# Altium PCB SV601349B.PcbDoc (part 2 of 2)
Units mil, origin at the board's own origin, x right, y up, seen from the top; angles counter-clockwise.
Board outline 3013 x 3112 mil, 4 copper layers (TOP, GND, PWR, BOTTOM), stack 60.36 mil thick; 123 components, 67 nets, 345 pads, 132 vias.
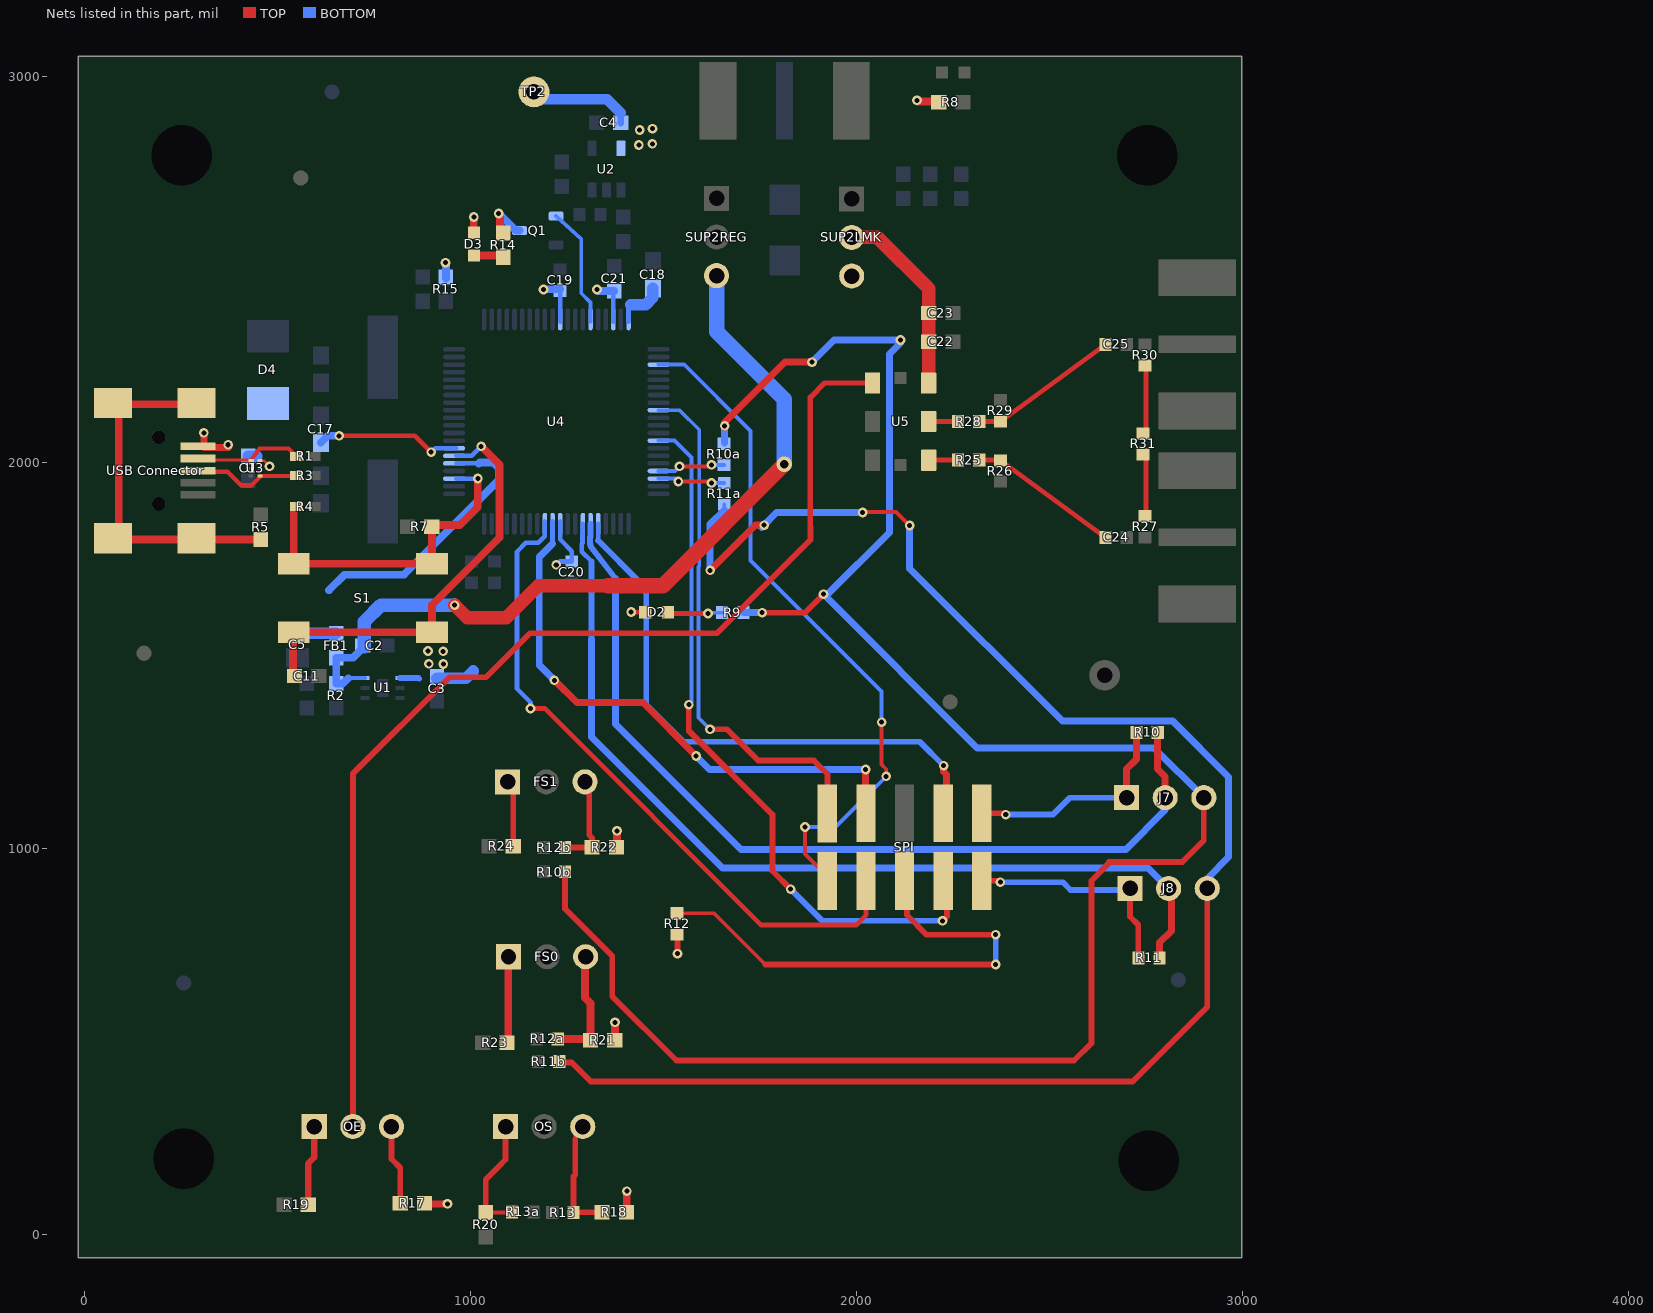
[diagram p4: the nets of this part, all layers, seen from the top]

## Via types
v1: diameter 25, hole 13, TOP to BOTTOM, 129 vias
v2: diameter 19.68, hole 7.87, TOP to BOTTOM, tented top, 1 vias
v3: diameter 40, hole 22, TOP to BOTTOM, 1 vias
v4: diameter 21, hole 9, TOP to BOTTOM, 1 vias

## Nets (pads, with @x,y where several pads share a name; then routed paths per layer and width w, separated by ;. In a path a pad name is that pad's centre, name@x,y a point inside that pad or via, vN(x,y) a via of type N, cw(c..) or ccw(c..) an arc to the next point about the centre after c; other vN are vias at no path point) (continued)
NetD2_2: D2.2 R9.2 | length 142
  TOP w10: D2.2@1511.53,1611 D2.2@1514.53,1608
  TOP w12: D2.2@1514.53,1608 v1(1615,1608)
  BOTTOM w10: v1(1615,1608) 1617,1610 R9.2@1651.44,1610
NetD3_2: D3.2 R14.2 | length 59.8
  TOP w20: D3.2@1016.4,2534.97 1075.47,2534.97 R14.2@1076,2534.44
NetFS0_1: FS0.1 R23.1 | length 214.5
  TOP w20: R23.1@1097.5,504.7 1097.5,718.5 FS0.1@1098,719
NetFS0_3: FS0.3 R12a.2 R21.2 | length 309
  TOP w10: R21.2@1307.5,506 R21.2@1310.5,503 ; 1308,601 1310.5,598.5
  TOP w20: R12a.2@1225.56,506 R21.2@1307.5,506 ; FS0.3@1298,719 1296,717 1296,613 1308,601 ; R21.2@1310.5,503 1310.5,598.5
NetFS1_1: FS1.1 R24.1 | length 168.4
  TOP w10: FS1.1@1107,1172 FS1.1@1110.5,1168.5
  TOP w15: R24.1@1110.5,1005 FS1.1@1110.5,1168.5
NetFS1_3: FS1.3 R12b.2 R22.2 | length 198.7
  TOP w15: R12b.2@1244.56,1002 1291.82,1002 ; FS1.3@1307,1172 1307,1034.2 1314.5,1026.7 1314.5,1023.7
NetJ7_2: J7.2 R10.1 U4.46 | length 2351.2
  TOP w18: R10.1@2779.56,1300 2779.56,1205.44 2799,1186 J7.2@2799,1131
  BOTTOM w10: J7.2@2799,1099 J7.2@2799,1131
  BOTTOM w15: U4.46@1310.58,1840.24 1310.58,1806.75 1309.27,1805.43 1309.27,1788.03 1310.58,1786.72 1310.58,1782.42 1375,1699
  BOTTOM w18: 1375,1699 1375,1322 1700,997 2697,997 J7.2@2799,1099
NetJ8_2: J8.2 R11.2 U4.47 | length 2416.6
  TOP w10: J8.2@2808,896 J8.2@2815,889
  TOP w18: R11.2@2784.56,716 2784.56,755.56 2815,786 J8.2@2815,889
  BOTTOM w12: U4.47@1290.9,1840.24 1290.9,1814.64 1289.77,1813.51 1289.77,1790.45 1288.06,1788.74 1288.06,1767.95 1289.06,1766.95 1313,1743
  BOTTOM w15: 1313,1542 1313,1743
  BOTTOM w18: 1313,1542 1313,1288 1652,949 2755,949 J8.2@2808,896
NetOE_1: OE.1 R19.1 | length 220.4
  TOP w16: R19.1@579.5,77 579.5,183.5 595,199 OE.1@595,291
NetOE_3: OE.3 R17.2 | length 198.6
  TOP w15: OE.3@795,291 795,195 817.5,172.5 817.5,101.7
NetOS_1: OS.1 R13a.2 R20.1 | length 312.9
  TOP w10: R20.1@1039,56.5 1105.94,56.5 R13a.2@1107.44,58
  TOP w15: R20.1@1039,56.5 1039,142 1072,175 1090.5,193.5 OS.1@1090.5,279
NetOS_3: OS.3 R13.2 R18.2 | length 307.3
  TOP w10: R13.2@1266.56,56 R13.2@1267.56,57 ; 1271,246 1271,259.5 OS.3@1290.5,279
  TOP w15: R13.2@1266.56,56 1266.56,149.56 1271,154 1271,246 ; R13.2@1267.56,57 R18.2@1340.5,57
NetQ1_1: Q1.1 U4.15 | length 312.3
  BOTTOM w10: Q1.1@1221.34,2637.2 1286.5,2578.3 1286.5,2437.3 1310.58,2413.22 U4.15@1310.58,2363.86
NetQ1_3: Q1.3 R14.1 | length 117.2
  TOP w20: v1@1075.7,2634.1 1076,2633.8 R14.1@1076,2589.56
  BOTTOM w20: v1(1072.7,2644.1) 1117,2599.8 Q1.3@1126.86,2599.8
NetR5_1: "USB Connector.6" "USB Connector.7" "USB Connector.8" "USB Connector.9" R5.1 | length 935
  TOP w20: 305.43,2150.2 88.89,2150.2 88.89,1799.8 305.42,1799.8 R5.1@457,1799.5
NetR10a_1: R10a.1 U4.37 | length 177
  TOP w10: v1(1541,1989) 1620,1989 v1(1624,1993)
  BOTTOM w10: U4.37@1486.76,1977.05 1529.05,1977.05 v1(1541,1989) ; v1@1623,1992 1623.44,1992.44 R10a.1@1656,1992.44
NetR11a_1: R11a.1 U4.38 | length 178.1
  TOP w10: v1(1538,1950) 1620,1950 v1(1624,1946)
  BOTTOM w10: U4.38@1486.76,1957.36 1530.64,1957.36 v1(1538,1950) ; v1@1621,1946 1621.44,1945.56 R11a.1@1657,1945.56
NetR12_2: R12.2 SPI.5 | length 1234
  TOP w10: R12.2@1535,831.56 1630.56,831.56 1763.12,699
  TOP w15: 1763.12,699 v1(2360,699) ; SPI.5@2130,853 2130,827 2181,776 v1(2360,776)
  BOTTOM w15: v1(2360,699) v1(2360,776)
NetR27_1: R27.1 R31.2 | length 159.3
  TOP w13: R27.1@2749,1860.12 R31.2@2749,2019.44
NetR30_2: R30.2 R31.1 | length 175.3
  TOP w13: R31.1@2749,2074.56 R30.2@2749,2249.88
OE: OE.2 U5.1@2040.74,2205 | length 2882.9
  TOP w14: 1880,1833 1880,2168 1917,2205 U5.1@2040.74,2205
  TOP w15: OE.2@695,291 695,1192.7 945.3,1443 1040,1443 1154,1557 1638,1557 1880,1799 1880,1833
OUT_N: R28.1 U5.5@2186.41,2105 | length 69.2
  TOP w13: U5.5@2186.41,2105 R28.1@2255.57,2105
OUT_P: R25.1 U5.4@2186.41,2005 | length 73
  TOP w13: U5.4@2186.41,2005 R25.1@2259.44,2005
PUR: R4.1 R7.2 S1.1 S1.2 U4.63 | length 873
  TOP w20: R4.1@548.38,1885 541.87,1878.49 S1.1@541.87,1736.58 S1.2@900.13,1736.58 900.13,1830.13 907,1837 972,1837 1018.5,1883.5 v1(1018.5,1957.6)
  BOTTOM w12: U4.63@963.14,1957.36 1018.26,1957.36 v1(1018.5,1957.6)
R_OUT_N: C25.2 R28.2 R29.1 | length 391.7
  TOP w13: R28.2@2317.56,2105 R29.1@2371.56,2105 ; R29.1@2372,2105.44 C25.2@2644.44,2305
R_OUT_P: C24.2 R25.2 R26.2 | length 394.2
  TOP w13: R25.2@2315.05,2005 R26.2@2371.56,2005 ; R26.2@2372,2004.56 C24.2@2644.44,1805
SCL: J8.3 R11a.2 R11b.1 | length 4332.6
  TOP w10: v1@2013,1871 2102,1871 v1(2137,1836)
  TOP w15: 1247.31,445 1262,445 1311,396 2715,396 2908,589 J8.3@2908,896
  TOP w18: v1@1619,1718 1737.7,1836.7 v1(1760.3,1836.7)
  BOTTOM w10: R11a.2@1657,1876 R11a.2@1657,1890.44 ; J8.3@2908,896 J8.3@2908,922
  BOTTOM w18: v1(1620.3,1719.7) 1620.3,1839.3 R11a.2@1657,1876 ; v1@1754,1831 1792.7,1869.7 v1(2015.3,1869.7) ; v1(2137,1836) 2137,1725 2532.5,1329.5 2818.5,1329.5 2963,1185 2963,977 J8.3@2908,922
SDA: J7.3 R9.1 R10a.2 R10b.1 | length 5353.3
  TOP w10: 2653,961 2653,964
  TOP w15: R10b.1@1244.56,939 1244.56,843.44 1367,721 1367,616 1533,450 2563,450 2608,495 2608,916 2653,961 ; v1(1755,1610) 1866,1610 v1(1914,1658) ; 2653,964 2843,964 2899,1020 J7.3@2899,1131
  TOP w18: v1@1658,2089 v1(1658,2094) 1658,2103 1814,2259 v1(1884,2259)
  BOTTOM w10: R10a.2@1656,2047.56 R10a.2@1658,2049.56 ; v1@2113.57,2308.57 v1(2113.57,2316.43)
  BOTTOM w18: R10a.2@1658,2049.56 v1(1658,2094) ; R9.1@1706.56,1610 v1(1755,1610) ; v1(1884,2259) 1941.43,2316.43 v1(2113.57,2316.43) ; v1@2113.57,2308.57 2085,2280 2085,1818 1925,1658 v1(1914,1658) 2312,1260 2770,1260 J7.3@2899,1131
U2A_3V3: C3.2 C19.2 C20.2 C21.2 D2.1 D3.1 R12.1 R15.1 U1.1 U4.11 U4.18 U4.50 | length 731
  TOP w10: R12.1@1535,776.44 R12.1@1535.8,775.64
  TOP w12: v1@1416.7,1611 D2.1@1452.47,1611
  TOP w15: v1(1535.8,726.9) R12.1@1535.8,775.64
  TOP w20: D3.1@1008.4,2594.03 v1(1008.4,2634.8)
  BOTTOM w12: v1(935,2516.5) v1@936,2515.5 ; v1(1221.8,1733.9) 1230.46,1742.56 C20.2@1262,1742.56 1262,1769.5 1231.84,1799.66 U4.50@1231.84,1846.14 ; U4.11@1231.84,2363.86 1231.84,2447.28 C19.2@1232,2447.44 ; U4.18@1369.64,2363.86 C21.2@1369.64,2443.5
  BOTTOM w15: U1.1@817.28,1440.59 864.81,1440.59 866.3,1439.1
  BOTTOM w20: R15.1@936,2475.56 v1@936,2515.5 ; v1(1188.7,2447) 1189.14,2447.44 C19.2@1232,2447.44 ; v1(1327.5,2447) 1331,2443.5 1369.64,2443.5 C21.2@1372,2443.5
  BOTTOM w30: C3.2@913,1440.56 987.96,1440.56 1006.4,1459
  other v1: 891.6,1477.4 929.4,1477 929,1510 889.7,1510.7 1415.8,1611.9
U2A_GPIO0: J7.1 R10.2 SPI.10 | length 561.6
  TOP w10: v1@2382.5,1090.5 v1(2386,1087) ; J7.1@2694,1136 J7.1@2699,1131
  TOP w15: SPI.10@2324,1090.5 v1@2382.5,1090.5
  TOP w18: J7.1@2699,1131 2699,1205 2724.44,1230.44 2724.44,1280.27
  BOTTOM w15: v1(2386,1087) 2508,1087 2552,1131 J7.1@2699,1131
U2A_GPIO1: J8.1 R11.1 SPI.9 | length 585.7
  TOP w10: SPI.9@2324,915.5 SPI.9@2339,900.5 ; v1@2368.5,915.5 v1(2372,912)
  TOP w15: SPI.9@2324,915.5 v1@2368.5,915.5 ; J8.1@2708,876.17 2708,823 2729.44,801.56 R11.1@2729.44,716
  BOTTOM w10: J8.1@2704,892 J8.1@2708,896
  BOTTOM w15: v1(2372,912) 2534,912 2554,892 J8.1@2704,892
U2A_GPIO3: SPI.7 U4.33 | length 1873.2
  TOP w10: SPI.7@2224,915.5 SPI.7@2234,905.5
  TOP w15: v1(1565,1372) 1565,1304 1782,1087 1782,941 v1(1829,894) ; v1(2222,812) 2234,824 SPI.7@2234,905.5
  BOTTOM w10: U4.33@1486.76,2055.79 1528.21,2055.79 1572,2012 1572,1379 v1(1565,1372)
  BOTTOM w15: v1(1829,894) 1911,812 v1(2222,812)
U2A_GPIO7: SPI.1 U4.23 | length 1778.1
  TOP w10: v1(1866,1055) 1866,985 1924,927 SPI.1@1924,915.5 ; v1(2064.4,1326.6) 2064.4,1216.6 2076.4,1204.6 v1(2076.4,1186)
  BOTTOM w10: U4.23@1486.76,2252.64 1553.36,2252.64 1725,2081 1725,1745 2064.4,1405.6 v1(2064.4,1326.6) ; v1(1866,1055) 1945.4,1055 v1(2076.4,1186)
U2A_MUXOUT: SPI.3 U4.52 | length 1670.6
  TOP w12: v1(1155,1362) 1192,1362 1753,801 1999,801 2024,826 2024,837.5
  BOTTOM w12: v1(1155,1362) 1155,1378 1120.2,1412.8 1120.2,1768.2 1143.1,1791.1 1175.37,1791.1 1192.47,1808.21 U4.52@1192.47,1846.14
U2A_SPI_CLK: SPI.8 U4.45 | length 1485.9
  TOP w10: SPI.8@2224,1090.5 SPI.8@2233,1099.5
  TOP w18: v1(2225,1214) 2225,1199 2233,1191 SPI.8@2233,1099.5
  BOTTOM w10: 1439.3,1686.7 1439.3,1687.7 ; 1551,1276 1552,1276
  BOTTOM w12: 1330.27,1796.73 U4.45@1330.27,1840.24
  BOTTOM w15: 1330.27,1796.73 1439.3,1687.7 ; 1439.3,1686.7 1455,1671 1455,1372 1551,1276 ; 1552,1276 2163,1276 v1(2225,1214)
U2A_SPI_CSB: SPI.2 U4.29 | length 1292.2
  TOP w15: v1(1620,1308) 1664,1308 1745,1227 1889,1227 1924,1192 1924,1167.5
  BOTTOM w10: U4.29@1486.76,2134.53 1541.47,2134.53 1592.27,2083.73 1592.27,1730.27 1590,1728 1590,1338 v1(1620,1308)
U2A_SPI_SDI: SPI.4 U4.51 | length 1447.8
  TOP w10: SPI.4@2007,1107.5 SPI.4@2024,1090.5
  TOP w18: v1(1217,1435) 1275,1377 1446,1377 v1(1584,1239) ; SPI.4@2023,1123.5 v1(2023,1204)
  BOTTOM w13: 1212.16,1788.56 U4.51@1212.16,1846.14
  BOTTOM w18: 1212.16,1788.56 1177.8,1754.2 1177.8,1474.2 v1(1217,1435) ; v1(1584,1239) 1619,1204 v1(2023,1204)
USB_N: "USB Connector.2" R1.2 U3.1 | length 262.8
  TOP w8: 310.86,2005 U3.1@430.54,2005
  TOP w10: 309.36,2006.5 310.86,2005
  TOP w11: U3.1@430.54,2005 453.28,2035 528.38,2035 R1.2@548.38,2015
USB_P: "USB Connector.3" R3.2 U3.4 | length 265.3
  TOP w11: 309.36,1975 370,1975 405,1940 432.66,1940 454.49,1961.83 U3.4@454.49,1964.32 547.69,1964.32 R3.2@548.38,1965
V18: C17.2 U4.67 | length 380.5
  TOP w12: v1(659.6,2068.2) 855.4,2068.2 v1(897.8,2025.8)
  BOTTOM w12: v1(897.8,2025.8) 908.1,2036.1 U4.67@963.14,2036.1
  BOTTOM w20: C17.2@612,2050 630.2,2068.2 v1(659.6,2068.2)
VBUS: "USB Connector.1" C1.2 C5.1 D4.1 FB1.1 U3.6 U4.65 | length 969.6
  TOP w7: U3.6@454.49,2003.69 464.31,2003.69 v1(479,1989)
  TOP w19: v1(309,2076) 309.36,2075.64 309.36,2037.99 372.89,2037.99 374.3,2039.4 372,2041.7 v1(372,2045)
  BOTTOM w12: U4.65@963.14,1996.73 1021.07,1996.73
  BOTTOM w20: 633,1668 673.4,1708.4 827.2,1708.4 1073.5,1954.7 1073.5,1984.6 1059.1,1999 1023.34,1999 1021.07,1996.73
  BOTTOM w30: C1.2@424,2015.5 446.37,2015.5 ; C5.1@552,1556.53 FB1.1@652,1556.5
VBUS_FILT: C2.2 FB1.2 R2.1 SUP2REG.3 U1.6 | length 2146
  TOP w35: v1(958.6,1629.7) 991.4,1596.9 1092.6,1596.9 1175.3,1679.6 1355.6,1679.6
  TOP w40: 1355.6,1679.6 1497.6,1679.6 v3(1812,1994)
  BOTTOM w10: 683,1440.59 U1.6@726.72,1440.59
  BOTTOM w20: 683,1440.59 668.91,1426.5 R2.1@652,1426.5 FB1.2@652,1493.5 695.5,1493.5 C2.2@724.44,1522.44
  BOTTOM w35: C2.2@724.44,1522.44 724.44,1586.24 768.1,1629.9 v1(958.6,1629.7)
  BOTTOM w40: SUP2REG.3@1637,2488 SUP2REG.3@1637,2483 1637,2338 1812,2163 v3(1812,1994)
VCORE: C18.2 U4.20 | length 134.8
  BOTTOM w12: U4.20@1409.01,2363.86 1409.01,2401.79 1414.71,2407.5
  BOTTOM w30: 1414.71,2407.5 1453.3,2407.5 1472,2426.2 C18.2@1472,2449.57 C18.2@1472,2450
VDD: C22.1 C23.1 R8.2 R17.1 R18.1 R21.1 R22.1 SUP2LMK.2 U5.6@2186.41,2205 | length 745
  TOP w10: R17.1@880.5,80 R17.1@881.5,79
  TOP w18: R17.1@881.5,79 v1(940,79)
  TOP w20: R21.1@1374,505.4 v1(1374,549) ; R22.1@1379,1003.4 v1@1379,1047 ; R18.1@1404.5,68 1404.5,111.6 v1(1404.8,111.9) ; v1@2157.5,2934 R8.2@2212.5,2934
  TOP w35: SUP2LMK.2@1987,2582 2054,2582 2186.5,2449.5 C23.1@2186.5,2386.2 2186.41,2312.2 2186.41,2310.31 U5.6@2186.41,2205
  other v1: 1379,1045 2156,2937
VDD_REG: C4.2 SUP2LMK.3 TP2.1 U2.5 | length 273.1
  BOTTOM w18: C4.2@1388.9,2878.6 1388.9,2904.1
  BOTTOM w28: TP2.1@1164,2959 1183,2940 1210,2940 1353,2940 1388.9,2904.1
  other v1: 1435.6,2821.5 1470.5,2824.5 1437.9,2860.2 1470.9,2863.6
VUSB: C11.2 S1.3 S1.4 U4.66 | length 1121.5
  TOP w20: C11.2@540,1446 540,1559.42 S1.4@900.13,1559.42 900.13,1630.13 1075,1805 1075,1993.3 v1(1027.5,2040.8)
  BOTTOM w12: U4.66@963.14,2016.42 1003.12,2016.42 v1(1027.5,2040.8)
pads on no net: "USB Connector.4" "USB Connector.10" "USB Connector.11" FID1.1 FID2.1 FID3.1 FID4.1 FID5.1 FID6.1 H1.1 H2.1 H3.1 H4.1 SH1_2_3.0 SH2_2_3.0 SH3_2_3.0 SH4_2_1.0 SH5_2_1.0 SH6_2_1.0 SH7_2_3.0 SH8_2_3.0 U1.2 U1.5 U2.4 U3.2 U3.5 U4.1 U4.2 U4.3 U4.4 U4.5 U4.6 U4.7 U4.8 U4.9 U4.10 U4.12 U4.13 U4.16 U4.17 U4.21 U4.22 U4.24 U4.25 U4.26 U4.27 U4.28 U4.30 U4.31 U4.32 U4.34 U4.35 U4.36 U4.39 U4.40 U4.41 U4.43 U4.44 U4.48 U4.53 U4.54 U4.55 U4.56 U4.71 U4.72 U4.73 U4.74 U4.75 U4.78 U4.79 U4.80 U5.1@2040.74,2189.25 U5.1@2040.74,2220.75 U5.2@2040.74,2089.25 U5.2@2040.74,2120.75 U5.3@2040.74,1989.25 U5.3@2040.74,2020.75 U5.4@2186.41,1989.25 U5.4@2186.41,2020.75 U5.5@2186.41,2089.25 U5.5@2186.41,2120.75 U5.6@2186.41,2189.25 U5.6@2186.41,2220.75

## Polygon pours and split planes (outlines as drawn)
VDD_REG on BOTTOM "Component Side-No Net 1" (solid, remove dead copper, pour order 13): 1370,2904.2 1482.2,2904.2 1493.4,2893 1505.7,2880.7 1505.7,2804.9 1477.5,2776.7 1406.9,2776.7 1375.2,2776.7 1368,2783.9 1363.3,2788.6 1363.3,2895.5 1363.3,2897.5 1370,2904.2
NetC12_2 on BOTTOM "Component Side-No Net 1" (solid, remove dead copper, pour order 16): 1223.3,2726.7 1281.2,2726.7 1291.9,2737.4 1293.3,2738.8 1326.9,2738.8 1329.9,2735.8 1329.9,2704.9 1329.9,2688.3 1319.6,2678 1300.3,2658.7 1300.3,2636.6 1300.3,2623.8 1297.2,2620.7 1266.3,2620.7 1260.2,2626.8 1258.8,2628.2 1258.8,2661.8 1251.5,2669.1 1228.9,2669.1 1228,2669.1 1218.8,2678.3 1218.8,2722.2 1223.3,2726.7
NetC10_2 on BOTTOM "Component Side-No Net 1" (solid, remove dead copper, pour order 17): 1320.9,2621.9 1363.8,2621.9 1375.6,2610.1 1375.9,2609.8 1501.8,2609.8 1575.7,2535.9 1661.9,2535.9 1671.2,2535.9 1689.9,2554.6 1691.7,2556.4 1691.7,2617.6 1672.6,2636.7 1616.6,2636.7 1598.9,2636.7 1515.9,2719.7 1495.4,2740.2 1382.7,2740.2 1376.2,2733.7 1376.2,2712.7 1376.2,2682.7 1361.3,2667.8 1360.9,2668.2 1327.4,2668.2 1320.9,2668.2 1318.6,2665.9 1318.6,2624.2 1320.9,2621.9
U2A_3V3 on BOTTOM "Component Side-No Net 1" (solid, remove dead copper, pour order 18): 800.1,1431.8 850.6,1431.8 857.5,1424.9 861.1,1421.3 963.7,1421.3 1036.8,1421.3 1059.4,1443.9 1059.4,1538 1053.7,1543.7 1037.98,1559.42 900.13,1559.42 887.72,1559.42 854.6,1526.3 846.6,1518.3 846.6,1479.9 832,1465.3 807.4,1465.3 803.5,1465.3 799.7,1461.5 797.4,1459.2 797.4,1448.8 797.4,1434.5 800.1,1431.8
VBUS on BOTTOM "TOP-No Net" (solid, remove dead copper, pour order 2): 477.05,1510.3 662.25,1510.3 671.55,1519.6 677.35,1525.4 677.35,1615.1 618.45,1674 533.75,1674 426.75,1674 369.35,1731.4 346.45,1754.3 346.45,1858.4 346.45,1966.9 349.25,1969.7 352.75,1973.2 399.15,1973.2 438.35,1973.2 444.05,1967.5 444.75,1966.8 458.65,1966.8 463.15,1966.8 471.35,1975 498.65,1975 541.15,2017.5 541.15,2164.9 526.25,2179.8 278.65,2179.8 250.05,2151.2 240.75,2141.9 240.75,1872.7 240.75,1610 305.05,1545.7 340.95,1509.8 476.25,1509.8
VDD_REG on TOP "TOP-No Net" (solid, pour order 8): 1388.9,2904.1 1482.3,2904.1 1505.7,2880.7 1525,2861.4 1525,2674 1525,2465 1563,2427 1587,2403 1816,2403 1830,2403 1955,2528 2029,2528 2048,2509 2048,2432 2012,2396 1919,2303 1626,2303 1482,2303 1390,2395 1384,2401 1384,2783 1384,2899.21 1388.9,2904.1
GND on GND (split plane): 2976.9,-40.9 4.1,-40.9 4.1,3030.9 2976.9,3030.9
VDD on PWR (split plane): 2976.9,-40.9 4.1,-40.9 4.1,1415.11 6,1414.93 1038,1414.93 1040.94,1415.22 1043.77,1416.07 1046.37,1417.47 1048.66,1419.34 1050.53,1421.63 1051.93,1424.23 1052.78,1427.06 1053.07,1429.93 1390.93,1429.93 1390.93,724 1391.22,721.06 1392.07,718.23 1393.47,715.63 1395.34,713.34 1476.34,632.34 1478.63,630.47 1481.23,629.07 1484.06,628.22 1487,627.93 1579,627.93 1580.46,628.07 1581.89,628.21 1581.92,628.21 1581.94,628.22 1583.33,628.64 1584.72,629.06 1584.75,629.07 1584.77,629.07 1586.05,629.76 1587.33,630.44 1587.35,630.46 1587.37,630.47 1588.5,631.39 1589.62,632.31 1589.64,632.33 1589.66,632.34 1590.58,633.47 1591.51,634.59 1591.52,634.61 1591.53,634.63 1592.22,635.91 1592.91,637.19 1592.91,637.21 1592.93,637.23 1593.35,638.62 1593.77,640.01 1593.78,640.04 1593.78,640.06 1593.93,641.51 1594.07,642.95 1598.07,1907.15 1597.93,1908.61 1597.8,1910.06 1525.57,2283.15 1525.57,3030.9 2976.9,3030.9
U2A_3V3 on PWR (split plane): 1495.43,2281.7 1495.57,2280.27 1495.7,2278.84 1567.92,1905.78 1563.97,658.07 1493.24,658.07 1421.07,730.24 1421.07,1445 1420.78,1447.94 1419.93,1450.77 1418.53,1453.37 1416.66,1455.66 1414.37,1457.53 1411.77,1458.93 1408.94,1459.78 1406,1460.07 1053,1460.07 1050.06,1459.78 1047.23,1458.93 1044.63,1457.53 1042.34,1455.66 1040.47,1453.37 1039.07,1450.77 1038.22,1447.94 1037.93,1445.07 6,1445.07 4.1,1444.89 4.1,3030.9 1495.43,3030.9

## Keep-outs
Keep-Out Layer:
  lines w10: -20,-65 2999,-65 2999,3055 -20,3055 -20,-65
  text ".Layer_Name" at 1016,-331 h60

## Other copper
TOP:
  text ".Layer_Name" at 1016,-331 h60
BOTTOM:
  text ".Layer_Name" at 1016,-331 h60
GND (plane layer: these items are gaps in the copper):
  text ".Layer_Name" at 1012,-341 h60
PWR (plane layer: these items are gaps in the copper):
  lines w10: 1038,1430 1053,1445
  lines w30: 6,1430 1038,1430 ; 1053,1445 1406,1445 1406,724 1487,643 1579,643 1583,1907.2 1510.5,2281.7 1510.5,3040.2
  text ".Layer_Name" at 1014,-343 h60

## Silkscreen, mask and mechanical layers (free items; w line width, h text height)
Top Overlay:
  region: 2193.5,1752 2133.5,1752 2133.5,1712 2193.5,1712
  region: -3631,3009.5 -3781,3009.5 -3781,2940 -3631,2940
  region: 1374,2179.5 1224,2179.5 1224,2110 1374,2110
  region: 2193.5,1814 2133.5,1814 2133.5,1774 2193.5,1774
  region: 2193.5,1686 2133.5,1686 2133.5,1646 2193.5,1646
  lines w5: 2382,2471 2408,2471 ; 2382,2472 2382,2527 2408,2527 2408,2472 ; 2382,2689 2408,2689 ; 2382,2690 2382,2745 2408,2745 2408,2690 ; 2458,2594 2484,2594 ; 2458,2595 2458,2650 2484,2650 2484,2595 ; 2459,2688 2485,2688 ; 2459,2689 2459,2744 2485,2744 2485,2689 ; 2462,2440 2488,2440 ; 2462,2441 2462,2496 2488,2496 2488,2441
  lines w7: 1567,2427 1567,2504 ; 1585,2743 2052,2743 ; 1701,2431 1701,2444 ; 1923,2432 1923,2500 ; 2447,2431 2447,2537 ; 2447,2554 2447,2660 ; 2447,2679 2447,2785 ; 2448,2538 2496,2538 ; 2448,2554 2496,2554 2496,2660 2448,2660 ; 2449,2431 2497,2431 ; 2449,2679 2495,2679 2495,2785 2449,2785 ; 2498,2431 2498,2537 ; 2372,2431 2418,2431 2418,2537 2372,2537 2372,2431 ; 2372,2556 2418,2556 2418,2662 2372,2662 2372,2556 ; 2372,2680 2372,2786 2418,2786 2418,2680 2372,2680
  lines w8: 1778,207 2268,207
  lines w10: 60,1144 175,1144 ; 241,1144 360,1144 ; 450,1144 810,1144 ; 1472,600 13,600 13,-48 2550,-48 2550,330 1474,330 1474,600 ; 1503,207 1600,207 ; 1650,207 1735,207 ; 13,640 13,1301 1472,1301 1472,640 13,640 ; 443,2882 1244,2882 1244,3035 443,3035 443,2882 ; 485.54,1508 485.54,1785 1353,1785 1353,1508 485.54,1508 ; 530,2440 1142,2440 1142,2663 530,2663 530,2440 ; 1215,2416 1215,2800 2629,2800 2629,2416 1215,2416 ; 1398,1516 1398,1721 1882,1721 1882,1516 1398,1516 ; 1631,694 2595,694 2595,1313 1631,1313 1631,694 ; 1990,1945 1990,2265 2232,2265 2232,1945 1990,1945 ; 2091,2885 2760,2885 2760,3035 2091,3035 2091,2885 ; 2628,774 2980,774 2980,1215 2628,1215 2628,774
  text "LMK61xx" at 2322,2973 h40
  text "3.3V REGOUT" at 648,2939 h40
  text "Supplied" at 2321,2911 h40
  text "Power Options For LMK61xx" at 1428,2760 h26
  text "." at 2392,2759 h35
  text "." at 2469,2758 h35
  text "." at 2392,2729 h35
  text "." at 2469,2728 h35
  text "USB Power=" at 2107,2719 h26
  text "." at 2392,2698 h35
  text "." at 2469,2697 h35
  text "VccEXT" at 1407,2686 h28
  text "VccEXT" at 1765,2686 h28
  text "." at 2392,2635 h35
  text "." at 2468,2634 h35
  text "VccEXT=" at 2158,2614 h26
  text "." at 2392,2605 h35
  text "." at 2468,2603 h35
  text "." at 2392,2574 h35
  text "3.3V" at 2180,2572 h26
  text "." at 2468,2569 h35
  text "MSP430" at 567,2567 h40
  text "Supplied" at 557,2513 h40
  text "." at 2392,2511 h35
  text "." at 2472,2510 h35
  text "VccEXT=" at 2149,2497 h26
  text "." at 2392,2480 h35
  text "." at 2472,2480 h35
  text "USB_PWR" at 1371,2461 h28
  text "REG" at 1829,2458.67 h28
  text "4.3V-5.5V" at 2106,2453 h26
  text "." at 2472,2449 h35
  text "." at 2392,2446 h35
  text "Reference PRO" at 324,2250 h60
  text "LMK61PD0A2" at 1393,2112 h60
  text "LMK61xx" at 1736,1936 h36
  text "Hardware Output Configuration:" at 1334,1856 h40
  text "LVPECL" at 2215,1774.01 h40
  text "LVDS" at 2215,1712.01 h40
  text "I2C Busy" at 1563,1647 h40
  text "HCSL" at 2215,1646.01 h40
  text "Firmware Update" at 879,1637 h32
  text "Pin Strapping Options  not enabled when" at 37,1381 h32
  text "headers ( FS0, FS1, and OS) are not populated" at 37,1328 h32
  text "Output Frequency" at 158,1236 h40
  text "Frequency" at 454,1171 h40
  text "FS1" at 63,1164.34 h40
  text "FS0" at 247.83,1164.34 h40
  text "GND" at 1017,1108 h40 r90
  text "Vdd" at 1402,1108 h40 r90
  text "GND" at 63,1070 h40
  text "GND" at 247.83,1070 h40
  text "100 MHz" at 455,1070 h40
  text "GPIO0" at 2647,1042 h27
  text "SDA" at 2873,1041 h30
  text "GND" at 63,1002 h40
  text "NC" at 247.83,1002 h40
  text "312.5 MHz" at 455,1002 h40
  text "see back of PCB" at 2639,986 h22
  text "GND" at 63,933 h40
  text "Vdd" at 247.83,933 h40
  text "125 MHz" at 455,933 h40
  text "NC" at 63,866 h40
  text "GND" at 247.83,866 h40
  text "106.25 MHz" at 454,866 h40
  text "GPIO1" at 2653,807 h27
  text "SCL" at 2886,805 h30
  text "NC" at 63,793 h40
  text "NC" at 247.83,793 h40
  text "156.25 MHz" at 455,793 h40
  text "SPI Serial Interface Output" at 1687,732 h35
  text "NC" at 63,730 h40
  text "Vdd" at 247.83,730 h40
  text "212.5 MHz" at 455,730 h40
  text "GND" at 1026,665 h40 r90
  text "Vdd" at 1405,665 h40 r90
  text "Vdd" at 63,664 h40
  text "GND" at 247.83,664 h40
  text "62.5 MHz" at 455,664 h40
  text "Output Config Driver" at 35,539 h40
  text "Should Match Hardware" at 35,475 h40
  text "Output Configuration" at 35,416 h40
  text "GND" at 1027,236 h40 r90
  text "Vdd" at 1400,236 h40 r90
  text "Output Config" at 1787,231 h40
  text "GND" at 528,226 h40 r90
  text "Vdd" at 896,226 h40 r90
  text "OE" at 1515,224.34 h40
  text "OS" at 1657,224.34 h40
  text "GND" at 1503.83,154 h40
  text "X" at 1690,154 h40
  text "DISABLED" at 1841,154 h40
  text "Vdd" at 1503.83,97 h40
  text "GND" at 1657,97 h40
  text "LVPECL" at 1851,97 h40
  text "Vdd" at 1503.83,38 h40
  text "NC" at 1657,38 h40
  text "LVDS" at 1856,38 h40
  text "Output En" at 742,-18 h28 r90
  text "Vdd" at 1503.83,-24 h40
  text "Vdd" at 1657,-24 h40
  text "HCSL" at 1864,-24 h40
  text ".Layer_Name" at 1016,-331 h60
Bottom Overlay:
  rectangle: 499,440 847,550.99
  lines w10: 1844,1055 2599,1055 ; 2013,773 2599,773 ; 1528,571 1528,1251 2641,1251 2641,571 1528,571
  text "IF J7 &  J8 Are populated" at 2598,1157 h40
  text "LMK61E2 Programming:" at 2598,1080 h40
  text "J7: SDA" at 2598,984 h40
  text "J8: SCL" at 2598,905 h40
  text "------------------------" at 2598,855 h40
  text "LMX Programming" at 2598,801 h40
  text "J7: GPIO0" at 2598,694 h40
  text "J8: GPIO1" at 2598,606 h40
  text "Rev .PCB_Rev" at 1249,587 h40
  text "SV601349-" at 1248,468 h45
  text ".Layer_Name" at 1016,-331 h60
Top Paste:
  text ".Layer_Name" at 1016,-331 h60
Bottom Paste:
  text ".Layer_Name" at 1016,-331 h60
Top Solder:
  text ".Layer_Name" at 1016,-331 h60
  text ".Layer_Name" at 1016,-331 h60
Bottom Solder:
  text ".Layer_Name" at 1016,-331 h60
Drill Guide:
  text ".Layer_Name" at 1016,-331 h60
M1 Board Outline:
  lines w10: -14,-59 2994,-59 2996,3048 -14,3048 -14,-59
  text ".Layer_Name" at 577,-858.49 h60
M2 Board Dimensions:
  rectangle: 125,-410.5 500,-285.5
  lines w7: 0,-160.5 0,-410.5 1000,-410.5 1000,-160.5 ; 125,-410.5 125,-160.5 ; 250,-410.5 250,-160.5 ; 500,-410.5 500,-160.5 ; 750,-410.5 750,-160.5
  text ".Layer_Name" at 577,-858.49 h60
M3 3D STEP Top:
  text ".Layer_Name" at 577,-858.49 h60
M4 3D STEP Bottom:
  text ".Layer_Name" at 577,-858.49 h60
M5 Assembly Top:
  lines w10: -292,-930.17 6308,-930.17 ; -292,-726.83 6310,-726.83 ; -292,-523.5 -292,-1133.5 3713,-1133.5 6310,-1133.5 6310,-523.5 -291.5,-523.5 -291.5,-1133.5 1284,-1133.5 ; 2173,-1133.5 2173,-523.5 ; 3440,-726.83 3440,-523.5 ; 4280,-726.83 4280,-523.5 ; 4902,-1140 4902,-937.17
  text "COMPONENTS MARKED 'DNP' SHOULD NOT BE POPULATED." at 1153.5,-318.5 h60
  text "ASSEMBLY VARIANT:" at 1153,-434 h60
  text ".VariantName" at 2189,-434 h60
  text "PCB VIEWED FROM TOP SIDE" at -228.5,-655.67 h60
  text "BOARD #:" at 2248,-655.67 h60
  text ".PRJ_Number" at 2793.5,-655.67 h60
  text "REV:" at 3638,-655.67 h60
  text ".PCB_Rev" at 3929.5,-655.67 h60
  text "SVN REV:" at 4476,-655.67 h60
  text ".VersionControl_RevNumber" at 4982,-655.67 h60
  text "IGNORE ->" at -228.5,-858.49 h60
  text "PLOT NAME =" at -228.5,-1064.34 h60
  text ".plot_File_Name" at 577,-1064.34 h60
  text "GENERATED    :" at 2250,-1064.34 h60
  text ".Print_Date" at 3119.5,-1064.34 h60
  text ".Print_Time" at 3848.5,-1064.34 h60
  text "TEXAS INSTRUMENTS" at 5113,-1064.34 h60
M6 Assembly Bottom:
  lines w10: -292.5,-727.33 6309.5,-727.33 ; -290.5,-930.67 6309.5,-930.67 ; 1115.5,-1140.5 1115.5,-937.67 ; 1737.5,-727.33 1737.5,-524 ; 2577.5,-727.33 2577.5,-524 ; 3844.5,-1134 3844.5,-524 ; 4733.5,-1134 6309,-1134 6309,-524 -292.5,-524 -292.5,-1134 2304.5,-1134 6309.5,-1134 6309.5,-524
  text "COMPONENTS MARKED 'DNP' SHOULD NOT BE POPULATED." at 6102,-318 h60
  text ".VariantName" at 5058,-434 h60
  text "ASSEMBLY VARIANT:" at 6097,-434 h60
  text ".VersionControl_RevNumber" at 1035.5,-656.17 h60
  text "SVN REV:" at 1541.5,-656.17 h60
  text ".PCB_Rev" at 2088,-656.17 h60
  text "REV:" at 2379.5,-656.17 h60
  text ".PRJ_Number" at 3224,-656.17 h60
  text "BOARD #:" at 3769.5,-656.17 h60
  text "PCB VIEWED FROM BOTTOM SIDE" at 6246,-656.17 h60
  text "IGNORE ->" at 2547.85,-858.49 h60
  text "TEXAS INSTRUMENTS" at 904.5,-1064.84 h60
  text ".Print_Time" at 2169,-1064.84 h60
  text ".Print_Date" at 2898,-1064.84 h60
  text "GENERATED    :" at 3767.5,-1064.84 h60
  text ".plot_File_Name" at 5440.5,-1064.84 h60
  text "PLOT NAME =" at 6246,-1064.84 h60
M9 Title Sheet:
  drawing of 57 lines, arcs and shapes, not listed
  text "1" at 739.84,8036.5 h70
  text "2" at 3235.5,8036.5 h70
  text "3" at 5724.84,8036.5 h70
  text "4" at 8231.51,8036.5 h70
  text "5" at 10730.5,8036.5 h70
  text "6" at 13235.5,8036.5 h70
  text "A" at -416.5,6893.5 h70
  text "A" at 14383.5,6893.5 h70
  text "B" at -416.5,4513.5 h70
  text "B" at 14383.5,4513.5 h70
  text "C" at -416.5,2138.5 h70
  text "C" at 14383.5,2138.5 h70
  text "PROJECT TITLE:" at 11343.5,277.5 h45
  text ".PRJ_Title" at 11393.5,144.17 h70
  text "DESIGNED FOR:" at 11343.5,-23.5 h45
  text ".PRJ_Customer" at 11393.5,-163.5 h70
  text "D" at -416.5,-231.5 h70
  text "D" at 14383.5,-231.5 h70
  text "FILE NAME:" at 11343.5,-323.5 h45
  text ".PCB_File_Name_No_Path" at 11393.5,-443.5 h70
  text "Texas Instruments (TI) and/or its licensors do not warrant the accuracy or completeness of this specification" at 6374,-605.34 h45
  text "ENGINEER:" at 11343.5,-613.5 h45
  text "LAYOUT BY:" at 12848.5,-613.5 h45
  text "or any information contained therein. TI and/or its licensors do not warrant that this design will meet" at 6329.01,-718 h45
  text ".PRJ_Engineer" at 11393.5,-768.49 h70
  text ".PCB_Layout" at 12899,-768.49 h70
  text "the specifications, will be suitable for your application or fit for any particular purpose, or will operate in" at 6329.01,-830.67 h45
  text ".Layer_Name" at 577,-858.49 h60
  text "ALTIUM DESIGNER VERSION:" at 12848.5,-923.5 h45
  text "an implementation. TI and/or its licensors do not warrant that the design is production worthy. You should" at 6329.01,-943.33 h45
  text "completely validate and test your design implementation to confirm the system functionality for your application." at 6374,-1056 h45
  text ".print_Scale" at 11393.5,-1056.83 h70
  text ".Application_BuildNumber" at 12899,-1056.83 h70
  text "1" at 739.84,-1263.5 h70
  text "2" at 3235.5,-1263.5 h70
  text "3" at 5724.84,-1263.5 h70
  text "4" at 8231.51,-1263.5 h70
  text "5" at 10730.5,-1263.5 h70
  text "6" at 13235.5,-1263.5 h70
M10 Fab Notes:
  drawing of 185 lines, arcs and shapes, not listed
  text "DIMENSIONS:" at 7133.04,7653 h40
  text "-- Rectangular shape with height minimized (SMA spacing + board stand offs)" at 7133.04,7517.66 h40
  text "Final PCB thickness 62 mil +/- 10%" at 7133.04,7355.67 h40
  text "STACKUP:" at 7133.04,7058.33 h40
  text "-- Layer 1: Device layer, Power/GPIO Jumper/Switches, RF microstrip from DUT" at 7133.04,6923 h40
  text "to SMA, USB connector, Silkscreens + Labeling" at 7133.04,6774.33 h40
  text "===== FR4: 8 mil" at 7133.04,6612.33 h40
  text "-- Layer 2: Ground Plane" at 7133.04,6477 h40
  text "===== FR4: 38 mil" at 7133.04,6315 h40
  text "-- Layer 3: Split Power planes for USB circuitry and DUT circuitry" at 7133.04,6179.66 h40
  text "===== FR4: 8 mil" at 7133.04,6017.67 h40
  text "DESIGN INFORMATION" at 12381.02,5910 h60
  text "-- Layer 4: USB circuitry" at 7133.04,5882.33 h40
  text "MIN. TRACK WIDTH:" at 11736.46,5730 h60
  text "8" at 12832.7,5730 h60
  text "MIL" at 12987.46,5730 h60
  text "MIN. CLEARANCE:" at 11736.46,5598 h60
  text "0.2" at 12772.7,5598 h60
  text "mm" at 12987.46,5598 h60
  text "Controlled Impedance Traces" at 7133.04,5585 h40
  text "MIN. VIA PAD SIZE:" at 11736.46,5466 h60
  text "24" at 12802.71,5466 h60
  text "MIL" at 12987.46,5466 h60
  text "-- TOP: 13 mil traces to be 50 ohm Zo +/- 5% reference to L2" at 7133.04,5423 h40
  text "0.05mm (2MIL)" at 12431.46,5324.29 h60
  text "MINIMUM ANNULAR RING" at 11407.23,5320 h60
  text "EXTERNAL" at 13139.46,5320 h60
  text "PER" at 11607.23,5202 h60
  text "IPC-D-275 CLASS 2 LEVEL C" at 11827.23,5202 h60
  text "MIL, HOLES" at 13315.46,5089.71 h60
  text "+/-" at 12923,5089 h60
  text "+/-" at 13777,5089 h60
  text "REGISTRATION TOLERANCES:" at 11407.23,5084 h60
  text "METAL" at 12607,5084 h60
  text "5" at 13183.2,5084 h60
  text "3" at 14016.2,5084 h60
  text "MIL" at 14132.46,5084 h60
  text "MATERIAL:" at 11332.46,4874.54 h60
  text "FR-4 High Tg" at 12318.9,4734.21 h60
  text "FR-408" at 11753.46,4725.64 h60
  text "X" at 12165.46,4725.64 h60
  text "OTHER" at 13241.46,4725.64 h60
  text "62 MIL (1.6mm) +/-10%" at 12073.56,4562.92 h60
  text "THICKNESS:" at 11407.23,4558.64 h60
  text "X" at 11945.4,4558.64 h60
  text "OTHER" at 13358.46,4558.64 h60
  text "TOLERANCE:" at 11407.23,4400.64 h60
  text "X" at 12246.53,4400.64 h60
  text "ANSI IPC-6012 TYPE 3 CLASS 2" at 12433.48,4400.64 h60
  text "OTHER +/-" at 12433.46,4244.64 h60
  text "BOW & TWIST:" at 11407.23,4087.64 h60
  text "X" at 12246.53,4087.64 h60
  text "ANSI IPC-6012 TYPE 3 CLASS 2" at 12433.48,4087.64 h60
  text "OTHER +/-" at 12433.46,3929.13 h60
  text "DRILLING:" at 11332.46,3790.64 h60
  text "REFERENCE:" at 11407.23,3673.64 h60
  text "X" at 12055.46,3673.64 h60
  text "AS SHOWN" at 12242.46,3673.64 h60
  text "X" at 12956.46,3673.64 h60
  text "NC_DRILL FILES" at 13093.46,3673.64 h60
  text "PTH MIN COPPER THICKNESS:" at 11407.23,3515.64 h60
  text "X" at 12757.46,3515.64 h60
  text "1MIL" at 12894.46,3515.64 h60
  text "OTHER" at 13391.46,3515.64 h60
  text "BOARD FINISH:" at 11332.46,3356.64 h60
  text "SILKSCREEN:" at 11487.68,3238.64 h60
  text "X" at 12436.46,3238.64 h60
  text "TOP" at 12562.46,3238.64 h60
  text "X" at 12946.46,3238.64 h60
  text "BOTTOM" at 13073.46,3238.64 h60
  text "SILKSCREEN COLOR:" at 11487.68,3071.64 h60
  text "X" at 12435.42,3071.64 h60
  text "WHITE" at 12562.46,3071.64 h60
  text "OTHER" at 13073.46,3071.64 h60
  text "SOLDER RESIST COLOR:" at 11487.68,2901.64 h60
  text "X" at 12055.42,2742.44 h60
  text "GREEN" at 12182.46,2742.44 h60
  text "BLUE" at 12773.46,2742.44 h60
  text "OTHER" at 13311.46,2742.44 h60
  text "IMMERSION GOLD (ENIG)" at 12393.46,2553.92 h60
  text "ENEPIG" at 13731,2550.64 h60
  text "SURFACE FINISH:" at 11332.46,2549.64 h60
  text "X" at 12206.51,2549.64 h60
  text "IMM. TIN/SILVER OR EQUIV" at 11662,2392.64 h60
  text "OTHER" at 13093.46,2392.64 h60
  text "ARRAY/PANEL:" at 11332.46,2213.64 h60
  text "CUT AND TRIM PER MECH LAYER 1" at 12393.46,2209.35 h60
  text "N.C. ROUTE" at 12393.46,2057.64 h60
  text "X" at 13072.46,2057.64 h60
  text "V. SCORE" at 13259.46,2057.64 h60
  text "CERTIFICATION:" at 11332.46,1920.64 h60
  text "MATERIALS AND WORKMANSHIP FOR ALL PCBS" at 12057.46,1920.64 h60
  text "TO MEET OR EXCEED THE REQUIREMENTS OF:" at 12057.46,1822.64 h60
  text "X" at 11683.96,1686.13 h60
  text "ANSI IPC-A-600F CLASS ->" at 11822.96,1686.13 h60
  text "X" at 13462.02,1686.13 h60
  text "2" at 13580.96,1686.14 h60
  text "1" at 13265.96,1684.64 h60
  text "3" at 13934.96,1684.64 h60
  text "X" at 11686.02,1526.64 h60
  text "UL 94V-0" at 11822.96,1526.64 h60
  text "X" at 12498.02,1526.64 h60
  text "RoHS" at 12634.96,1526.64 h60
  text "OTHER" at 13279.36,1526.64 h60
  text "PER ORDER" at 13676.42,1526.64 h60
  text "ADDITIONAL REQUIREMENTS:" at 11332.46,1385.64 h60
  text "MICROSECTION:" at 11407.23,1270.64 h60
  text "YES" at 12312.96,1270.64 h60
  text "REQUIRED" at 13174.46,1114.49 h60
  text "BARE BOARD ELEC. TEST:" at 11407.23,1111.64 h60
  text "NONE" at 12712.96,1111.64 h60
  text "X" at 13047.46,1111.64 h60
  text "PER ORDER" at 13766.46,1111.64 h60
  text "MANUFACTURER'S UL:" at 11407.23,954.64 h60
  text "RAIL" at 12572.96,950.35 h60
  text "METAL" at 13064.77,950.35 h60
  text "X" at 13440,950 h60
  text "SILK" at 13576.46,950.35 h60
  text ".Layer_Name" at 710,-894.49 h60
M11 Gerber Information:
  lines w10: -292,-930.17 6308,-930.17 ; -292,-726.83 6310,-726.83 ; -292,-523.5 -292,-1133.5 3713,-1133.5 6310,-1133.5 6310,-523.5 -291.5,-523.5 -291.5,-1133.5 1284,-1133.5 ; 2173,-1133.5 2173,-523.5 ; 3440,-726.83 3440,-523.5 ; 4280,-726.83 4280,-523.5 ; 4902,-1140 4902,-937.17
  text "ALL ARTWORK VIEWED FROM TOP SIDE" at -228.5,-655.67 h60
  text "BOARD #:" at 2248,-655.67 h60
  text ".PRJ_Number" at 2793.5,-655.67 h60
  text "REV:" at 3638,-655.67 h60
  text ".PCB_Rev" at 3929.5,-655.67 h60
  text "SVN REV:" at 4476,-655.67 h60
  text ".VersionControl_RevNumber" at 4982,-655.67 h60
  text "LAYER NAME =" at -228.5,-858.49 h60
  text "PLOT NAME =" at -228.5,-1064.34 h60
  text ".plot_File_Name" at 577,-1064.34 h60
  text "GENERATED    :" at 2250,-1064.34 h60
  text ".Print_Date" at 3119.5,-1064.34 h60
  text ".Print_Time" at 3848.5,-1064.34 h60
  text "TEXAS INSTRUMENTS" at 5113,-1064.34 h60
M12 Stackup:
  drawing of 295 lines, arcs and shapes, not listed
  text "Layer" at 55.5,5353.5 h60
  text "Name" at 465.41,5353.5 h60
  text "Material" at 1395.16,5353.5 h60
  text "Thickness" at 2254.92,5353.5 h60
  text "Constant" at 2904.76,5353.5 h60
  text "Board Layer Stack" at 3474.62,5353.5 h60
  text "1" at 55.5,5233.5 h60
  text "Top Overlay" at 465.41,5233.5 h60
  text "2" at 55.5,5113.5 h60
  text "Top Solder" at 465.41,5113.5 h60
  text "Solder Resist" at 1395.16,5113.5 h60
  text "0.80mil" at 2254.92,5113.5 h60
  text "3.5" at 2904.76,5113.5 h60
  text "3" at 55.5,4993.5 h60
  text "TOP" at 465.41,4993.5 h60
  text "Copper" at 1395.16,4993.5 h60
  text "1.78mil" at 2254.92,4993.5 h60
  text "4" at 55.5,4873.5 h60
  text "Dielectric1" at 465.41,4873.5 h60
  text "FR-4" at 1395.16,4873.5 h60
  text "8.00mil" at 2254.92,4873.5 h60
  text "4.3" at 2904.76,4873.5 h60
  text "5" at 55.5,4753.5 h60
  text "GND" at 465.41,4753.5 h60
  text "Copper" at 1395.16,4753.5 h60
  text "1.40mil" at 2254.92,4753.5 h60
  text "6" at 55.5,4633.5 h60
  text "Dielectric2" at 465.41,4633.5 h60
  text "FR-4" at 1395.16,4633.5 h60
  text "38.00mil" at 2254.92,4633.5 h60
  text "4.3" at 2904.76,4633.5 h60
  text "7" at 55.5,4513.5 h60
  text "PWR" at 465.41,4513.5 h60
  text "Copper" at 1395.16,4513.5 h60
  text "1.40mil" at 2254.92,4513.5 h60
  text "8" at 55.5,4393.5 h60
  text "Dielectric3" at 465.41,4393.5 h60
  text "FR-4" at 1395.16,4393.5 h60
  text "8.00mil" at 2254.92,4393.5 h60
  text "4.3" at 2904.76,4393.5 h60
  text "9" at 55.5,4273.5 h60
  text "BOTTOM" at 465.41,4273.5 h60
  text "Copper" at 1395.16,4273.5 h60
  text "1.78mil" at 2254.92,4273.5 h60
  text "10" at 55.5,4153.5 h60
  text "Bottom Solder" at 465.41,4153.5 h60
  text "Solder Resist" at 1395.16,4153.5 h60
  text "0.80mil" at 2254.92,4153.5 h60
  text "3.5" at 2904.76,4153.5 h60
  text "11" at 55.5,4033.5 h60
  text "Bottom Overlay" at 465.41,4033.5 h60
  text ".Layer_Name" at 577,-858.49 h60
M13 Component Bodies Top:
  text ".Layer_Name" at 1016,-331 h60
M14 Component Bodies Bottom:
  text ".Layer_Name" at 1016,-331 h60
M15 Courtyards Top:
  text ".Layer_Name" at 1016,-331 h60
M16 Courtyards Bottom:
  text ".Layer_Name" at 1016,-331 h60
Drill Drawing:
  text ".legend" at 6196.5,1849.5 h60
  text "Drill Table" at 6221.5,1664.5 h60
  text ".Layer_Name" at 1016,-331 h60

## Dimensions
-10,3048 to -30,-59 on M2 Board Dimensions
2994,-77 to -14,-79 on M2 Board Dimensions
0,-410.5 to 1000,-410.5 on M2 Board Dimensions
